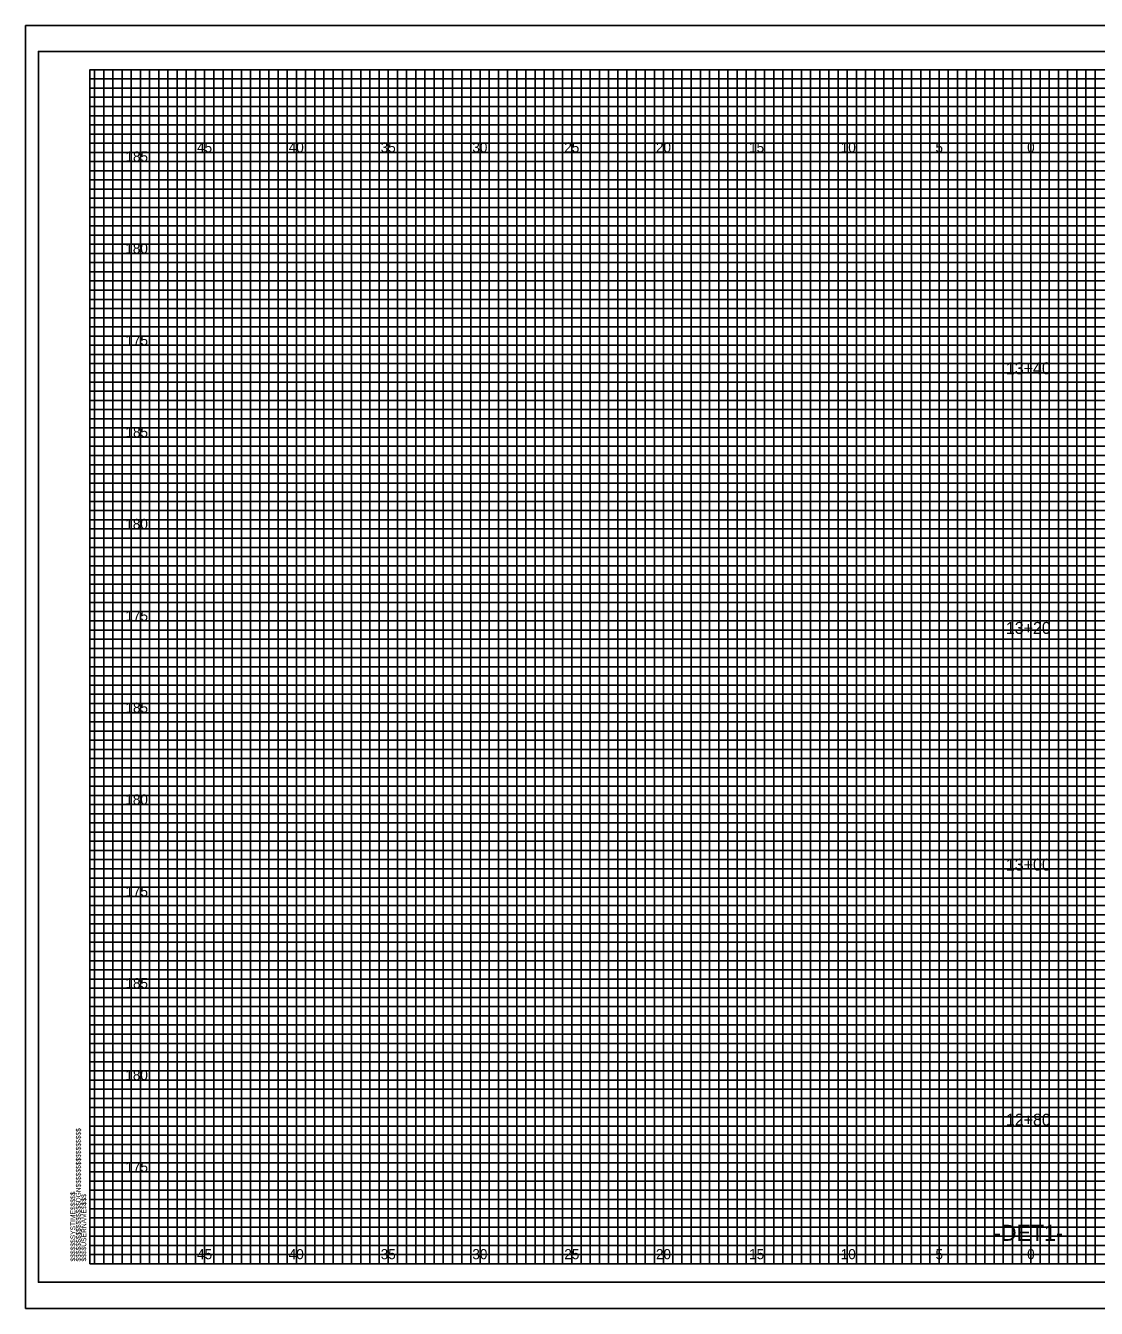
# Model space of a CAD drawing. Extents: x -4 to 103, y -2 to 280.
# Drawn here: x -3.5 to 54.8, y -2.4 to 67.4 of the extents above; entities that cross this region are included whole.
import ezdxf

# ---------------------------------------------------------------- set-up
doc = ezdxf.new("R2010")
doc.units = 0
for name, color, linetype in [('Exist XS Center Line Elevation Label', 7, 'Continuous'), ('Old_Level_63', 7, 'Continuous'), ('Prop XS Dump Level', 7, 'Continuous'), ('Prop XS EOT Tick Mark', 7, 'Continuous'), ('Prop XS Finish Grade Earthwork', 7, 'Continuous'), ('Prop XS Pvmt Edge Slope', 7, 'Continuous'), ('Prop XS SE Text', 7, 'Continuous'), ('Prop XS Subgrade Earthwork', 7, 'Continuous'), ('Sheet Cutting Line CELL', 7, 'Continuous'), ('Sheet Plot Border Inside CELL', 7, 'Continuous'), ('Sheet Plot Border Outside CELL', 7, 'Continuous')]:
    doc.layers.add(name, color=color, linetype=linetype)

msp = doc.modelspace()

# ---------------------------------------------------------------- linework, layer by layer
at = {"layer": 'Exist XS Center Line Elevation Label'}
for points in [[(1.25, 0), (1.25, 65), (3.75, 65), (3.75, 0), (6.25, 0), (6.25, 65), (8.75, 65), (8.75, 0), (11.25, 0), (11.25, 65), (13.75, 65), (13.75, 0), (16.25, 0), (16.25, 65), (18.75, 65), (18.75, 0), (21.25, 0), (21.25, 65), (23.75, 65), (23.75, 0), (26.25, 0), (26.25, 65), (28.75, 65), (28.75, 0), (31.25, 0), (31.25, 65), (33.75, 65), (33.75, 0), (36.25, 0), (36.25, 65), (38.75, 65), (38.75, 0), (41.25, 0), (41.25, 65), (43.75, 65), (43.75, 0), (46.25, 0), (46.25, 65), (48.75, 65), (48.75, 0), (51.25, 0), (51.25, 65), (53.75, 65), (53.75, 0)], [(102.5, 60), (0, 60), (0, 62.5), (74.25, 62.5)], [(102.5, 55), (0, 55), (0, 57.5), (102.5, 57.5)], [(102.5, 50), (0, 50), (0, 52.5), (102.5, 52.5)], [(102.5, 45), (0, 45), (0, 47.5), (102.5, 47.5)], [(102.5, 40), (0, 40), (0, 42.5), (102.5, 42.5)], [(102.5, 35), (0, 35), (0, 37.5), (102.5, 37.5)], [(102.5, 30), (0, 30), (0, 32.5), (102.5, 32.5)], [(102.5, 25), (0, 25), (0, 27.5), (102.5, 27.5)], [(102.5, 20), (0, 20), (0, 22.5), (102.5, 22.5)], [(102.5, 15), (0, 15), (0, 17.5), (102.5, 17.5)], [(102.5, 10), (0, 10), (0, 12.5), (102.5, 12.5)], [(102.5, 5), (0, 5), (0, 7.5), (102.5, 7.5)], [(0, 2.5), (102.5, 2.5)]]:
    msp.add_lwpolyline(points, dxfattribs=at)
at = {"layer": 'Old_Level_63'}
msp.add_lwpolyline([(102.5, 65), (0, 65), (0, 0), (102.5, 0)], close=True, dxfattribs=at)
at = {"layer": 'Prop XS Dump Level'}
for p, q in [((1.25, 0), (1.25, 65)), ((3.75, 0), (3.75, 65)), ((6.25, 0), (6.25, 65)), ((8.75, 0), (8.75, 65)), ((11.25, 0), (11.25, 65)), ((13.75, 0), (13.75, 65)), ((16.25, 0), (16.25, 65)), ((18.75, 0), (18.75, 65)), ((21.25, 0), (21.25, 65)), ((23.75, 0), (23.75, 65)), ((26.25, 0), (26.25, 65)), ((28.75, 0), (28.75, 65)), ((31.25, 0), (31.25, 65)), ((33.75, 0), (33.75, 65)), ((36.25, 0), (36.25, 65)), ((38.75, 0), (38.75, 65)), ((41.25, 0), (41.25, 65)), ((43.75, 0), (43.75, 65)), ((46.25, 0), (46.25, 65)), ((48.75, 0), (48.75, 65)), ((51.25, 0), (51.25, 65)), ((53.75, 0), (53.75, 65)), ((0, 62.5), (74.25, 62.5)), ((0, 60), (102.5, 60)), ((0, 57.5), (102.5, 57.5)), ((0, 55), (102.5, 55)), ((0, 52.5), (102.5, 52.5)), ((0, 50), (102.5, 50)), ((0, 47.5), (102.5, 47.5)), ((0, 45), (102.5, 45)), ((0, 42.5), (102.5, 42.5)), ((0, 40), (102.5, 40)), ((0, 37.5), (102.5, 37.5)), ((0, 35), (102.5, 35)), ((0, 32.5), (102.5, 32.5)), ((0, 30), (102.5, 30)), ((0, 27.5), (102.5, 27.5)), ((0, 25), (102.5, 25)), ((0, 22.5), (102.5, 22.5)), ((0, 20), (102.5, 20)), ((0, 17.5), (102.5, 17.5)), ((0, 15), (102.5, 15)), ((0, 12.5), (102.5, 12.5)), ((0, 10), (102.5, 10)), ((0, 7.5), (102.5, 7.5)), ((0, 5), (102.5, 5)), ((0, 2.5), (102.5, 2.5))]:
    msp.add_line(p, q, dxfattribs=at)
at = {"layer": 'Prop XS SE Text'}
for points in [[(0.25, 0), (0.25, 65), (0.75, 65), (0.75, 0), (1.75, 0), (1.75, 65), (2.25, 65), (2.25, 0), (2.75, 0), (2.75, 65), (3.25, 65), (3.25, 0), (4.25, 0), (4.25, 65), (4.75, 65), (4.75, 0), (5.25, 0), (5.25, 65), (5.75, 65), (5.75, 0), (6.75, 0), (6.75, 65), (7.25, 65), (7.25, 0), (7.75, 0), (7.75, 65), (8.25, 65), (8.25, 0), (9.25, 0), (9.25, 65), (9.75, 65), (9.75, 0), (10.25, 0), (10.25, 65), (10.75, 65), (10.75, 0), (11.75, 0), (11.75, 65), (12.25, 65), (12.25, 0), (12.75, 0), (12.75, 65), (13.25, 65), (13.25, 0), (14.25, 0), (14.25, 65), (14.75, 65), (14.75, 0), (15.75, 0), (15.25, 0), (15.25, 65), (15.75, 65), (15.75, 0), (16.75, 0), (16.75, 65), (17.25, 65), (17.25, 0), (17.75, 0), (17.75, 65), (18.25, 65), (18.25, 0), (19.25, 0), (19.25, 65), (19.75, 65), (19.75, 0), (20.25, 0), (20.25, 65), (20.75, 65), (20.75, 0), (21.75, 0), (21.75, 65), (22.25, 65), (22.25, 0), (22.75, 0), (22.75, 65), (23.25, 65), (23.25, 0), (24.25, 0), (24.25, 65), (24.75, 65), (24.75, 0), (25.25, 0), (25.25, 65), (25.75, 65), (25.75, 0), (26.75, 0), (26.75, 65), (27.25, 65), (27.25, 0), (27.75, 0), (27.75, 65), (28.25, 65), (28.25, 0), (29.25, 0), (29.25, 65), (29.75, 65), (29.75, 0), (30.25, 0), (30.25, 65), (30.75, 65), (30.75, 0)], [(30.75, 0), (31.75, 0), (31.75, 65), (32.25, 65), (32.25, 0), (32.75, 0), (32.75, 65), (33.25, 65), (33.25, 0), (34.25, 0), (34.25, 65), (34.75, 65), (34.75, 0), (35.25, 0), (35.25, 65), (35.75, 65), (35.75, 0), (36.75, 0), (36.75, 65), (37.25, 65), (37.25, 0), (37.75, 0), (37.75, 65), (37.75, 0)], [(38.25, 65), (38.25, 0), (39.25, 0), (39.25, 65), (39.75, 65), (39.75, 0), (40.25, 0), (40.25, 65), (40.75, 65), (40.75, 0), (41.75, 0), (41.75, 65), (42.25, 65), (42.25, 0), (42.75, 0), (42.75, 65), (43.25, 65), (43.25, 0), (43.75, 0), (44.25, 0), (44.25, 65), (44.75, 65), (44.75, 0), (45.25, 0), (45.25, 65), (45.75, 65), (45.75, 0), (46.75, 0), (46.75, 65), (47.25, 65), (47.25, 0), (47.75, 0), (47.75, 65), (48.25, 65), (48.25, 0), (49.25, 0), (49.25, 65), (49.75, 65), (49.75, 0), (50.25, 0), (50.25, 65), (50.75, 65), (50.75, 0), (51.75, 0), (51.75, 65), (52.25, 65), (52.25, 0), (52.75, 0), (52.75, 65), (53.25, 65), (53.25, 0), (54.25, 0), (54.25, 65), (54.75, 65), (54.75, 0), (55.25, 0)], [(0, 62), (0, 63), (74.25, 63), (74.25, 63.5), (0, 63.5), (0, 64), (74.25, 64), (74.25, 64.5), (0, 64.5)], [(102.5, 62), (0, 62)], [(102.5, 61), (0, 61), (0, 61.5), (102.5, 61.5)], [(102.5, 59.5), (0, 59.5), (0, 60.5), (102.5, 60.5)], [(102.5, 58.5), (0, 58.5), (0, 59), (102.5, 59)], [(102.5, 57), (0, 57), (0, 58), (102.5, 58)], [(102.5, 56), (0, 56), (0, 56.5), (102.5, 56.5)], [(102.5, 54.5), (0, 54.5), (0, 55.5), (102.5, 55.5)], [(102.5, 53.5), (0, 53.5), (0, 54), (102.5, 54)], [(0, 53), (102.5, 53)], [(102.5, 52), (0, 52)], [(102.5, 51), (0, 51), (0, 51.5), (102.5, 51.5)], [(102.5, 49.5), (0, 49.5), (0, 50.5), (102.5, 50.5)], [(102.5, 48.5), (0, 48.5), (0, 49), (102.5, 49)], [(102.5, 47), (0, 47), (0, 48), (102.5, 48)], [(102.5, 46), (0, 46), (0, 46.5), (102.5, 46.5)], [(102.5, 44.5), (0, 44.5), (0, 45.5), (102.5, 45.5)], [(102.5, 43.5), (0, 43.5), (0, 44), (102.5, 44)], [(102.5, 42), (0, 42), (0, 43), (102.5, 43)], [(102.5, 41), (0, 41), (0, 41.5), (102.5, 41.5)], [(102.5, 39.5), (0, 39.5), (0, 40.5), (102.5, 40.5)], [(102.5, 38.5), (0, 38.5), (0, 39), (102.5, 39)], [(102.5, 37), (0, 37), (0, 38), (102.5, 38)], [(102.5, 36), (0, 36), (0, 36.5), (102.5, 36.5)], [(102.5, 34.5), (0, 34.5), (0, 35.5), (102.5, 35.5)], [(102.5, 33.5), (0, 33.5), (0, 34), (102.5, 34)], [(102.5, 32), (0, 32), (0, 33), (102.5, 33)], [(102.5, 31), (0, 31), (0, 31.5)], [(0, 31.5), (102.5, 31.5)], [(102.5, 29.5), (0, 29.5), (0, 30.5), (102.5, 30.5)], [(102.5, 28.5), (0, 28.5), (0, 29), (102.5, 29)], [(102.5, 27), (0, 27), (0, 28), (102.5, 28)], [(102.5, 26), (0, 26), (0, 26.5), (102.5, 26.5)], [(102.5, 24.5), (0, 24.5), (0, 25.5), (102.5, 25.5)], [(102.5, 23.5), (0, 23.5), (0, 24), (102.5, 24)], [(102.5, 22), (0, 22), (0, 23), (102.5, 23)], [(102.5, 21), (0, 21), (0, 21.5), (102.5, 21.5)], [(102.5, 19.5), (0, 19.5), (0, 20.5), (102.5, 20.5)], [(102.5, 18.5), (0, 18.5), (0, 19), (102.5, 19)], [(102.5, 17), (0, 17), (0, 18), (102.5, 18)], [(102.5, 16), (0, 16), (0, 16.5), (102.5, 16.5)], [(102.5, 14.5), (0, 14.5), (0, 15.5), (102.5, 15.5)], [(102.5, 13.5), (0, 13.5), (0, 14), (102.5, 14)], [(102.5, 12), (0, 12), (0, 13), (102.5, 13)], [(102.5, 11), (0, 11), (0, 11.5), (102.5, 11.5)], [(102.5, 9.5), (0, 9.5), (0, 10.5), (102.5, 10.5)], [(102.5, 8.5), (0, 8.5), (0, 9), (102.5, 9)], [(102.5, 7), (0, 7), (0, 8), (102.5, 8)], [(102.5, 6), (0, 6), (0, 6.5), (102.5, 6.5)], [(102.5, 4.5), (0, 4.5), (0, 5.5), (102.5, 5.5)], [(102.5, 3.5), (0, 3.5), (0, 4), (102.5, 4)], [(102.5, 2), (0, 2), (0, 3), (102.5, 3)], [(102.5, 1), (0, 1), (0, 1.5), (102.5, 1.5)], [(0, 0.5), (102.5, 0.5)]]:
    msp.add_lwpolyline(points, dxfattribs=at)
at = {"layer": 'Sheet Cutting Line CELL'}
for p, q in [((-3.5, 67.4), (103.4, 67.4)), ((-3.5, 67.4), (-3.5, -2.425)), ((-3.5, -2.425), (103.4, -2.425))]:
    msp.add_line(p, q, dxfattribs=at)
at = {"layer": 'Sheet Plot Border Inside CELL'}
msp.add_lwpolyline([(103, 66), (-2.8, 66), (-2.8, -1), (103, -1)], close=True, dxfattribs=at)
at = {"layer": 'Sheet Plot Border Outside CELL'}
msp.add_lwpolyline([(103.4, 67.4), (-3.5, 67.4), (-3.5, -2.425), (103.4, -2.425)], close=True, dxfattribs=at)

# ---------------------------------------------------------------- texts
at = {"layer": 'Exist XS Center Line Elevation Label'}
msp.add_text('040397', height=0.0025, rotation=90, dxfattribs=at).set_placement((-0.001, 64.986))
at = {"layer": 'Old_Level_63'}
for s, p in [('$$$$$$$$$$$$$$$$DGN$$$$$$$$$$$$$$$$', (-0.5, 0.125)), ('$$$$$$SYSTIME$$$$$', (-0.797, 0.125)), ('$$$$USERNAME$$$$', (-0.2, 0.125))]:
    msp.add_text(s, height=0.2625, rotation=90, dxfattribs=at).set_placement(p)
at = {"layer": 'Prop XS EOT Tick Mark'}
for s, p in [('13+40', (49.893, 48.424)), ('13+20', (49.893, 34.289)), ('13+00', (49.893, 21.406)), ('12+80', (49.893, 7.519))]:
    msp.add_text(s, height=0.65, dxfattribs=at).set_placement(p)
at = {"layer": 'Prop XS Finish Grade Earthwork'}
msp.add_text('-DET1-', height=0.875, dxfattribs=at).set_placement((49.238, 1.25))
at = {"layer": 'Prop XS Pvmt Edge Slope'}
for s, p in [('45', (5.84, 60.5)), ('40', (10.831, 60.5)), ('35', (15.84, 60.5)), ('30', (20.831, 60.5)), ('25', (25.84, 60.5)), ('20', (30.831, 60.5)), ('15', (35.906, 60.5)), ('10', (40.897, 60.5)), ('5', (46.057, 60.5)), ('0', (51.049, 60.5)), ('0', (51.049, 60.5)), ('45', (5.84, 0.25)), ('40', (10.831, 0.25)), ('35', (15.84, 0.25)), ('30', (20.831, 0.25)), ('25', (25.84, 0.25)), ('20', (30.831, 0.25)), ('15', (35.906, 0.25)), ('10', (40.897, 0.25)), ('5', (46.057, 0.25)), ('0', (51.049, 0.25)), ('0', (51.049, 0.25))]:
    msp.add_text(s, height=0.55, dxfattribs=at).set_placement(p)
at = {"layer": 'Prop XS Subgrade Earthwork'}
for s, p in [('185', (1.938, 60)), ('180', (1.93, 55)), ('175', (1.938, 50)), ('185', (1.938, 45)), ('180', (1.93, 40)), ('175', (1.938, 35)), ('185', (1.938, 30)), ('180', (1.93, 25)), ('175', (1.938, 20)), ('185', (1.938, 15)), ('180', (1.93, 10)), ('175', (1.938, 5))]:
    msp.add_text(s, height=0.55, dxfattribs=at).set_placement(p)

doc.saveas('drawing.dxf')
